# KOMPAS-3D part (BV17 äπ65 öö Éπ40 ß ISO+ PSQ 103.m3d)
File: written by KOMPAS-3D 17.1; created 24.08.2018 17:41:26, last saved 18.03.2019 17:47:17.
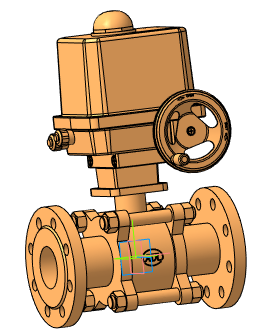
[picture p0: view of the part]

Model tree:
1. Операция без истории:2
